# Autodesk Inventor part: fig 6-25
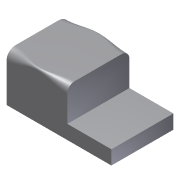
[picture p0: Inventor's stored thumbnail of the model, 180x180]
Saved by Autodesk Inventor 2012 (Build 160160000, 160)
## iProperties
Created: 2004-05
Part Number: fig 6-25
Document SubType Name: Modeling
Designer: CADCIM Technologies
Manufacturer: Standard
Standards Organization: Custom
Density: 1 g/cm^3
Material: Default
Author: CADCIM Technologies
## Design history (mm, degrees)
node "Sketch1"
sketch "Sketch2"
  geometry: L1 (0.098, 47.711)-(0.098, 0.049); L2 (0.098, 0.049)-(-105.483, 0.049); L3 (-105.483, 0.049)-(-105.483, 14.192); L4 (-105.483, 14.192)-(-61.139, 14.192); L5 (-61.139, 14.192)-(-61.139, 47.711); L6 (-61.139, 47.711)-(0.098, 47.711)
  constraints: 12 end point, 3 parallel, 2 perpendicular, 1 vertical
extrude "Extrusion1" new body sketch "Sketch2" stored distance "d0" = 62.5; taper "d1" = 0 deg
fillet "Fillet9" dims "d61" = 10, "d62" = 8, "d63" = 2, "d64" = 5
fillet "Fillet10" dims "d65" = 8, "d66" = 10, "d67" = 2, "d68" = 5
body "Solid1"
